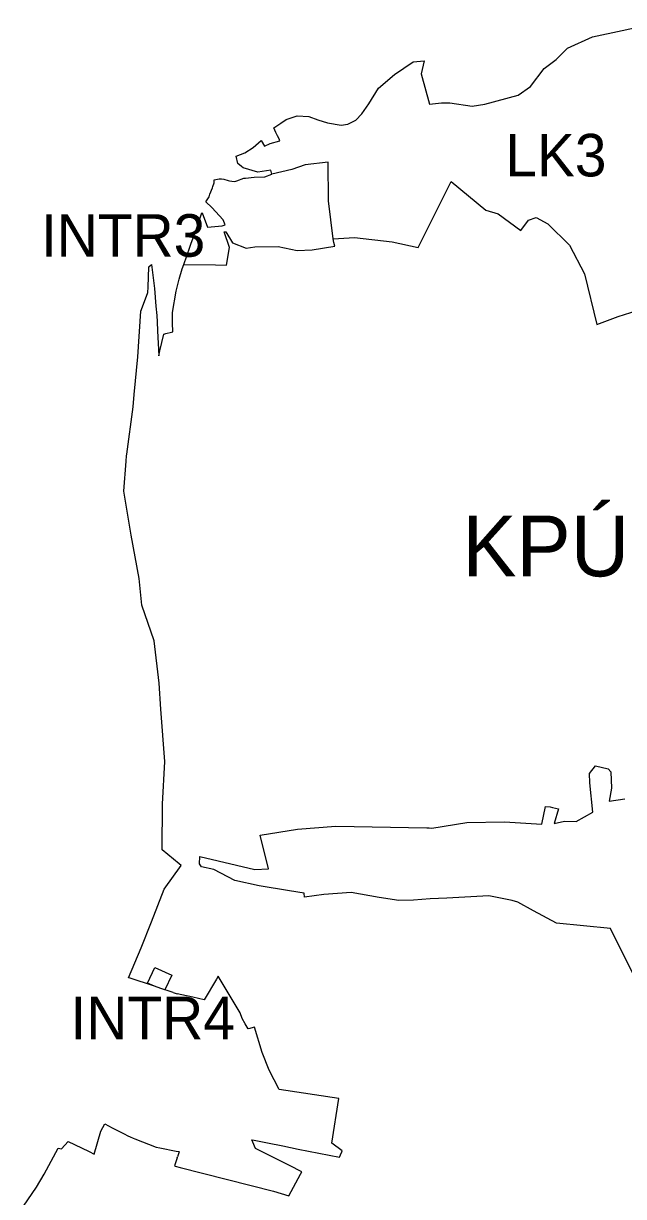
# Model space of a CAD drawing. Extents: x -754919 to -751903, y -1143879 to -1139906.
# Drawn here: x -754771 to -753784, y -1141930 to -1139999 of the extents above; entities that cross this region are included whole.
import ezdxf

# ---------------------------------------------------------------- set-up
doc = ezdxf.new("R2010")
doc.units = 0
for name, color, linetype in [('Vrstva 13', 7, 'Continuous'), ('Vrstva 2', 7, 'Continuous'), ('Vrstva 4', 7, 'Continuous'), ('Vrstva 6', 7, 'Continuous')]:
    doc.layers.add(name, color=color, linetype=linetype)

msp = doc.modelspace()

# ---------------------------------------------------------------- linework, layer by layer
at = {"layer": 'Vrstva 13'}
for p, q in [((-753786.41, -1140010.3), (-753733.98, -1139998.76)), ((-753875.97, -1140039.31), (-753834.83, -1140020.77)), ((-753834.83, -1140020.77), (-753786.41, -1140010.3)), ((-753895.05, -1140058.31), (-753875.97, -1140039.31)), ((-754160.65, -1140082.72), (-754130.36, -1140062.1)), ((-754130.36, -1140062.1), (-754112.06, -1140060.19)), ((-754112.06, -1140060.19), (-754116.82, -1140081.44)), ((-753914.37, -1140073.05), (-753895.05, -1140058.31)), ((-754116.82, -1140081.44), (-754103.56, -1140131.37)), ((-753936.85, -1140102.63), (-753914.37, -1140073.05)), ((-754187.17, -1140105.38), (-754160.65, -1140082.72)), ((-754203.22, -1140130.89), (-754187.17, -1140105.38)), ((-754012.13, -1140131.62), (-753957.41, -1140116.75)), ((-753957.41, -1140116.75), (-753936.85, -1140102.63)), ((-754214.7, -1140147.72), (-754203.22, -1140130.89)), ((-754103.56, -1140131.37), (-754083.4, -1140129.39)), ((-754083.4, -1140129.39), (-754069.96, -1140129.52)), ((-754069.96, -1140129.52), (-754032.9, -1140134.69)), ((-754032.9, -1140134.69), (-754012.13, -1140131.62)), ((-754347.97, -1140162.69), (-754339.37, -1140156.79)), ((-754339.37, -1140156.79), (-754321.21, -1140150.81)), ((-754321.21, -1140150.81), (-754301.75, -1140151.86)), ((-754301.75, -1140151.86), (-754287.03, -1140157.39)), ((-754287.03, -1140157.39), (-754271.01, -1140162.55)), ((-754237.73, -1140164.54), (-754224.28, -1140157.95)), ((-754224.28, -1140157.95), (-754214.7, -1140147.72)), ((-754359.3, -1140170.51), (-754347.97, -1140162.69)), ((-754355.94, -1140178.23), (-754359.3, -1140170.51)), ((-754353.32, -1140183.59), (-754355.94, -1140178.23)), ((-754271.01, -1140162.55), (-754248.64, -1140166.35)), ((-754248.64, -1140166.35), (-754237.73, -1140164.54)), ((-754393.49, -1140203.1), (-754380.34, -1140191.64)), ((-754380.34, -1140191.64), (-754374.97, -1140200.61)), ((-754374.97, -1140200.61), (-754365.72, -1140196.59)), ((-754365.72, -1140196.59), (-754349.36, -1140191.71)), ((-754350.91, -1140188.52), (-754353.32, -1140183.59)), ((-754349.36, -1140191.71), (-754350.91, -1140188.52)), ((-754421.43, -1140217.32), (-754407.23, -1140211.93)), ((-754407.23, -1140211.93), (-754393.49, -1140203.1)), ((-754418.83, -1140229.13), (-754421.43, -1140217.32)), ((-754412.92, -1140234.19), (-754418.83, -1140229.13)), ((-754410.07, -1140236.63), (-754412.92, -1140234.19)), ((-754457.51, -1140255.9), (-754449.19, -1140254.5)), ((-754449.19, -1140254.5), (-754445.73, -1140254.42)), ((-754445.73, -1140254.42), (-754441.84, -1140255.12)), ((-754441.84, -1140255.12), (-754434.89, -1140257.13)), ((-754420.17, -1140257.61), (-754409.07, -1140253.52)), ((-754385.63, -1140243.5), (-754410.07, -1140236.63)), ((-754409.07, -1140253.52), (-754407.14, -1140253.44)), ((-754407.14, -1140253.44), (-754405.88, -1140253.29)), ((-754405.88, -1140253.29), (-754391.59, -1140251.51)), ((-754391.59, -1140251.51), (-754374.51, -1140251.17)), ((-754364.15, -1140240.32), (-754385.63, -1140243.5)), ((-754374.51, -1140251.17), (-754362.96, -1140246.58)), ((-754362.96, -1140246.58), (-754364.15, -1140240.32)), ((-754464.68, -1140279.95), (-754460.47, -1140269.22)), ((-754460.47, -1140269.22), (-754459.87, -1140267.32)), ((-754459.87, -1140267.32), (-754457.89, -1140261.04)), ((-754457.89, -1140261.04), (-754457.51, -1140255.9)), ((-754434.89, -1140257.13), (-754432.41, -1140257.67)), ((-754432.41, -1140257.67), (-754428.63, -1140258.49)), ((-754428.63, -1140258.49), (-754423.9, -1140258.67)), ((-754423.9, -1140258.67), (-754420.17, -1140257.61)), ((-754471.2, -1140292.56), (-754467.85, -1140287.25)), ((-754461.7, -1140301.52), (-754471.2, -1140292.56)), ((-754467.85, -1140287.25), (-754465.77, -1140283.95)), ((-754465.77, -1140283.95), (-754464.68, -1140279.95)), ((-754487.45, -1140338.24), (-754477.7, -1140310.74)), ((-754477.7, -1140310.74), (-754477.29, -1140310.39)), ((-754477.29, -1140310.39), (-754468.49, -1140334.31)), ((-754443.02, -1140322.07), (-754461.7, -1140301.52)), ((-754468.49, -1140334.31), (-754444.63, -1140332.14)), ((-754444.63, -1140332.14), (-754439.5, -1140329.97)), ((-754440.57, -1140327.58), (-754443.02, -1140322.07)), ((-754439.5, -1140329.97), (-754440.57, -1140327.58)), ((-754495.85, -1140361.91), (-754487.45, -1140338.24)), ((-754507.83, -1140395.67), (-754497.73, -1140367.2)), ((-754497.73, -1140367.2), (-754495.85, -1140361.91)), ((-754566.53, -1140432.75), (-754565.34, -1140399.33)), ((-754565.34, -1140399.33), (-754560.67, -1140395.31)), ((-754560.67, -1140395.31), (-754555.88, -1140435.06)), ((-754515.49, -1140419.6), (-754510.21, -1140402.39)), ((-754510.21, -1140402.39), (-754507.83, -1140395.67)), ((-754520.1, -1140439.23), (-754515.49, -1140419.6)), ((-754570.78, -1140452.11), (-754566.84, -1140441.34)), ((-754566.84, -1140441.34), (-754566.53, -1140432.75)), ((-754555.88, -1140435.06), (-754553.7, -1140464.36)), ((-754526.1, -1140474.8), (-754520.1, -1140439.23)), ((-754578.17, -1140472.28), (-754570.78, -1140452.11)), ((-754553.7, -1140464.36), (-754552.01, -1140479.69)), ((-754583.32, -1140547.25), (-754578.17, -1140472.28)), ((-754552.01, -1140479.69), (-754551.5, -1140489.83)), ((-754526.41, -1140491.5), (-754526.19, -1140479.69)), ((-754526.19, -1140479.69), (-754526.1, -1140474.8)), ((-754551.5, -1140489.83), (-754550.76, -1140504.66)), ((-754550.76, -1140504.66), (-754548.68, -1140546.1)), ((-754529.95, -1140507.58), (-754525.76, -1140506.56)), ((-754525.76, -1140506.56), (-754526.41, -1140491.5)), ((-754546.85, -1140537.85), (-754540.71, -1140510.23)), ((-754540.71, -1140510.23), (-754537.13, -1140509.35)), ((-754537.13, -1140509.35), (-754534.79, -1140508.77)), ((-754534.79, -1140508.77), (-754529.95, -1140507.58)), ((-754548.68, -1140546.1), (-754546.85, -1140537.85)), ((-754589.29, -1140609.77), (-754583.32, -1140547.25)), ((-754591.2, -1140629.73), (-754589.29, -1140609.77)), ((-754601.48, -1140707.57), (-754591.2, -1140629.73)), ((-754602.46, -1140719.46), (-754601.74, -1140710.72)), ((-754601.74, -1140710.72), (-754601.48, -1140707.57)), ((-754606.53, -1140768.61), (-754602.46, -1140719.46)), ((-754594.24, -1140840.97), (-754606.53, -1140768.61)), ((-754580.9, -1140912.12), (-754594.24, -1140840.97)), ((-754576.56, -1140956.06), (-754580.9, -1140912.12)), ((-754556.33, -1141014.98), (-754576.56, -1140956.06)), ((-754548.42, -1141084.92), (-754556.33, -1141014.98)), ((-754545.27, -1141127.29), (-754548.42, -1141084.92)), ((-754538.87, -1141213.4), (-754545.27, -1141127.29)), ((-754542.69, -1141284.02), (-754538.87, -1141213.4)), ((-754543.4, -1141359.09), (-754542.69, -1141284.02)), ((-754515.43, -1141382.1), (-754543.4, -1141359.09)), ((-754540.05, -1141424.02), (-754512.21, -1141384.75)), ((-754512.21, -1141384.75), (-754515.43, -1141382.1)), ((-754560.81, -1141477.56), (-754540.05, -1141424.02)), ((-754577.72, -1141520.22), (-754560.81, -1141477.56)), ((-754598.69, -1141569.51), (-754577.72, -1141520.22)), ((-754450.95, -1141566.72), (-754453.86, -1141571.66)), ((-754414.67, -1141627.55), (-754450.95, -1141566.72)), ((-754597.79, -1141569.81), (-754598.69, -1141569.51)), ((-754555.84, -1141583.65), (-754597.79, -1141569.81)), ((-754545.51, -1141587.06), (-754555.84, -1141583.65)), ((-754538.82, -1141589.26), (-754545.51, -1141587.06)), ((-754453.86, -1141571.66), (-754473.95, -1141605.74)), ((-754535.26, -1141590.44), (-754538.82, -1141589.26)), ((-754524.92, -1141593.85), (-754535.26, -1141590.44)), ((-754524.92, -1141593.85), (-754518.71, -1141595.9)), ((-754510.82, -1141597.63), (-754518.71, -1141595.9)), ((-754492.77, -1141601.6), (-754510.82, -1141597.63)), ((-754473.95, -1141605.74), (-754492.77, -1141601.6)), ((-754411.64, -1141636.39), (-754414.67, -1141627.55)), ((-754406.42, -1141645.52), (-754411.64, -1141636.39)), ((-754401.81, -1141653.58), (-754406.42, -1141645.52)), ((-754398.91, -1141652.86), (-754401.81, -1141653.58)), ((-754393.61, -1141651.54), (-754398.91, -1141652.86)), ((-754391.09, -1141650.91), (-754393.61, -1141651.54)), ((-754378.64, -1141692.54), (-754391.09, -1141650.91)), ((-754367.42, -1141721.67), (-754378.64, -1141692.54)), ((-754350.47, -1141753.77), (-754367.42, -1141721.67)), ((-754252.36, -1141768.53), (-754350.47, -1141753.77)), ((-754264.1, -1141841.94), (-754252.36, -1141768.53)), ((-754644.4, -1141821.88), (-754637.54, -1141810.14)), ((-754637.54, -1141810.14), (-754625.29, -1141816.41)), ((-754625.29, -1141816.41), (-754616.72, -1141820.8)), ((-754708.81, -1141850.97), (-754697.98, -1141839.09)), ((-754697.98, -1141839.09), (-754664.51, -1141855.21)), ((-754655.09, -1141859.75), (-754644.4, -1141821.88)), ((-754616.72, -1141820.8), (-754605.87, -1141826.35)), ((-754605.87, -1141826.35), (-754599.51, -1141829.61)), ((-754599.51, -1141829.61), (-754595.95, -1141831.43)), ((-754595.95, -1141831.43), (-754591.04, -1141833.36)), ((-754591.04, -1141833.36), (-754588.03, -1141834.54)), ((-754588.03, -1141834.54), (-754553.36, -1141848.16)), ((-754393.87, -1141840.47), (-754395.59, -1141836.36)), ((-754395.59, -1141836.36), (-754392.1, -1141837.05)), ((-754392.1, -1141837.05), (-754369.67, -1141841.51)), ((-754737.57, -1141893.08), (-754714.53, -1141849.8)), ((-754714.53, -1141849.8), (-754708.81, -1141850.97)), ((-754664.51, -1141855.21), (-754661.43, -1141856.7)), ((-754661.43, -1141856.7), (-754657.34, -1141858.67)), ((-754553.36, -1141848.16), (-754547.31, -1141849.39)), ((-754547.31, -1141849.39), (-754520.27, -1141854.89)), ((-754520.27, -1141854.89), (-754515.8, -1141855.8)), ((-754515.09, -1141855.94), (-754516.72, -1141860.83)), ((-754515.8, -1141855.8), (-754515.09, -1141855.94)), ((-754389.53, -1141850.87), (-754393.87, -1141840.47)), ((-754333.97, -1141878.69), (-754389.53, -1141850.87)), ((-754369.67, -1141841.51), (-754344.71, -1141846.46)), ((-754344.71, -1141846.46), (-754319.27, -1141851.51)), ((-754319.27, -1141851.51), (-754251.4, -1141864.98)), ((-754246.93, -1141854.41), (-754264.1, -1141841.94)), ((-754249.67, -1141860.9), (-754247.58, -1141855.94)), ((-754247.58, -1141855.94), (-754246.93, -1141854.41)), ((-754657.34, -1141858.67), (-754655.09, -1141859.75)), ((-754518.48, -1141866.13), (-754522.8, -1141879.11)), ((-754518.48, -1141866.13), (-754517.97, -1141864.59)), ((-754516.72, -1141860.83), (-754517.97, -1141864.59)), ((-754251.4, -1141864.98), (-754249.67, -1141860.9)), ((-754750.23, -1141914.45), (-754737.57, -1141893.08)), ((-754522.8, -1141879.11), (-754521.73, -1141879.44)), ((-754521.73, -1141879.44), (-754513.45, -1141881.97)), ((-754513.45, -1141881.97), (-754360.18, -1141920.67)), ((-754334.64, -1141928.32), (-754315.66, -1141893)), ((-754313.49, -1141888.95), (-754333.97, -1141878.69)), ((-754315.66, -1141893), (-754313.49, -1141888.95)), ((-754771.49, -1141945.5), (-754750.23, -1141914.45)), ((-754360.18, -1141920.67), (-754334.64, -1141928.32))]:
    msp.add_line(p, q, dxfattribs=at)
at = {"layer": 'Vrstva 2'}
for points in [[(-754438.58, -1140341.99), (-754427.46, -1140360.1), (-754404.77, -1140368.64), (-754390.74, -1140366.22), (-754352.61, -1140365.62), (-754321.24, -1140372.64), (-754296.64, -1140371.19), (-754259.18, -1140365.14), (-754260.68, -1140359.57), (-754261.71, -1140353.34), (-754269.76, -1140290.79), (-754270.29, -1140227.13), (-754308.17, -1140231.54), (-754329.69, -1140238.91), (-754362.96, -1140246.58)], [(-754507.83, -1140395.67), (-754455.44, -1140396.25), (-754437.29, -1140396.44), (-754432.59, -1140367.48), (-754441.17, -1140341.79), (-754438.58, -1140341.99)], [(-754555.84, -1141583.65), (-754567.47, -1141578.28), (-754555.07, -1141552.42), (-754527.13, -1141565.1), (-754538.82, -1141589.26)]]:
    msp.add_lwpolyline(points, dxfattribs=at)
at = {"layer": 'Vrstva 4'}
for points in [[(-754261.71, -1140353.34), (-754226.5, -1140351.34), (-754164.77, -1140358.18), (-754121.98, -1140367.31), (-754067.73, -1140259.06), (-754010.66, -1140305.94), (-753990.23, -1140312.3), (-753952.78, -1140339.4), (-753940.29, -1140322.3), (-753927.9, -1140318.09), (-753908.58, -1140328.52), (-753872.87, -1140363.97), (-753848.15, -1140410.68), (-753827.69, -1140494.07), (-753792.76, -1140481.05), (-753751.18, -1140467.9), (-753700.94, -1140464.01), (-753706.63, -1140431.58), (-753708.59, -1140404.46), (-753703.24, -1140381.08), (-753693.42, -1140360)], [(-753754.56, -1141591.18), (-753805.66, -1141488.69), (-753894.3, -1141479.65), (-753932.05, -1141459.47), (-753957.84, -1141445.38), (-753967.22, -1141442.27), (-754005.78, -1141434.58), (-754074.57, -1141438.61), (-754102.32, -1141439.76), (-754129.73, -1141442.06), (-754154, -1141442.25), (-754186.02, -1141437.34), (-754232.46, -1141429.15), (-754276.94, -1141432.45), (-754309.09, -1141436.68), (-754309.34, -1141430.09), (-754333.58, -1141426.65), (-754383.84, -1141418.08), (-754423.56, -1141409.75), (-754458.05, -1141391.57), (-754478.73, -1141386.96), (-754481.64, -1141381.98), (-754481.33, -1141370.2), (-754390.52, -1141391.19), (-754368.09, -1141390.3), (-754381.83, -1141334.73), (-754320.78, -1141325.15), (-754257.6, -1141319.85), (-754107.7, -1141322.8), (-754103.83, -1141322.64), (-754099.41, -1141323.58), (-754042.02, -1141314), (-753980.16, -1141312.89), (-753918.59, -1141316.73), (-753912.34, -1141287.52), (-753904.88, -1141288.44), (-753900.66, -1141289.26), (-753891.3, -1141291.61), (-753898.31, -1141315.4), (-753881.2, -1141311.73), (-753862.2, -1141312.22), (-753834.45, -1141296.92), (-753839.54, -1141248.61), (-753840.25, -1141233.4), (-753830.3, -1141220.65), (-753809.4, -1141225.66), (-753804.66, -1141230.47), (-753803.72, -1141257.48), (-753807.44, -1141278.76), (-753781.77, -1141275.3)]]:
    msp.add_lwpolyline(points, dxfattribs=at)

# ---------------------------------------------------------------- texts
for s, height, p in [('LK3', 70, (-753978.63, -1140250.53)), ('KPÚ', 100, (-754049.34, -1140908.85))]:
    msp.add_text(s, height=height, dxfattribs=at).set_placement(p)
at = {"layer": 'Vrstva 6'}
for s, p in [('INTR3', (-754742.71, -1140382.71)), ('INTR4', (-754694.04, -1141670.7))]:
    msp.add_text(s, height=70, dxfattribs=at).set_placement(p)

doc.saveas('drawing.dxf')
